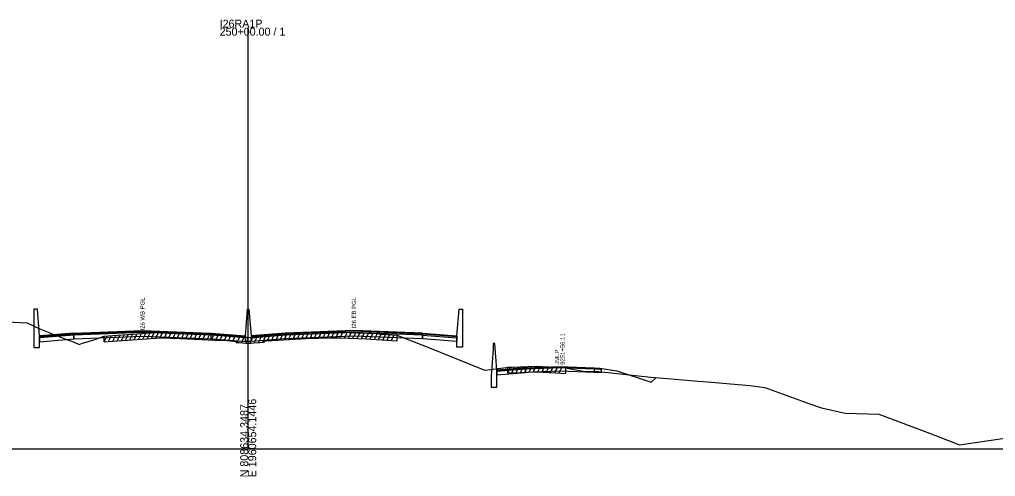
# Model space of a CAD drawing. Extents: x 1017 to 19997, y -1947 to 50737.
# Drawn here: x 10520 to 10861.4, y -9.7 to 150.1 of the extents above; entities that cross this region are included whole.
import ezdxf

# ---------------------------------------------------------------- set-up
doc = ezdxf.new("R2010")
doc.units = 0
for name, color, linetype in [('RD_GPK_XS_Cell', 7, 'Continuous'), ('RD_XS_Base', 7, 'Continuous'), ('RD_XS_ExGround', 7, 'Continuous'), ('RD_XS_ExPaveRet', 7, 'Continuous'), ('RD_XS_Greenside', 7, 'Continuous'), ('RD_XS_MedBWall', 7, 'Continuous'), ('RD_XS_Pave', 7, 'Continuous'), ('RD_XS_PaveOvlay', 7, 'Continuous'), ('RD_XS_TieSlope', 7, 'Continuous'), ('RD_XS_TX_Notes', 7, 'Continuous')]:
    doc.layers.add(name, color=color, linetype=linetype)

msp = doc.modelspace()

# ---------------------------------------------------------------- linework, layer by layer
at = {"layer": 'RD_GPK_XS_Cell'}
for p, q in [((10600, 0), (10600, 147.22)), ((10000, 0), (10600, 0)), ((10600, 0), (11200, 0))]:
    msp.add_line(p, q, dxfattribs=at)
at = {"layer": 'RD_XS_Base'}
for points in [[(10539, 39.73), (10527, 38.77)], [(10527, 38.77), (10527, 37.43)], [(10527, 37.43), (10539, 38.39)], [(10539, 38.39), (10539, 39.73)], [(10539.05, 38.39), (10539, 38.39)], [(10539.05, 39.73), (10539.05, 38.39)], [(10539.05, 38.39), (10563, 39.36), (10587, 38.39)], [(10587, 38.39), (10587, 39.73)], [(10599, 38.79), (10587, 39.73)], [(10587, 38.39), (10599, 37.45)], [(10599, 37.45), (10599, 38.79)], [(10601, 37.48), (10601, 38.82)], [(10613, 38.43), (10601, 37.48)], [(10613, 38.43), (10613, 39.77)], [(10660.95, 38.43), (10637, 39.39), (10613, 38.43)], [(10660.95, 38.43), (10660.95, 39.77)], [(10661, 38.43), (10660.95, 38.43)], [(10661, 39.77), (10661, 38.43)], [(10661, 39.76), (10673, 38.8)], [(10661, 38.42), (10661, 39.76)], [(10673, 37.46), (10661, 38.42)], [(10673, 38.8), (10673, 37.46)], [(10697, 27.96), (10687, 27.16)], [(10697, 27.96), (10709, 28.44), (10721, 27.96)], [(10697, 26.63), (10697, 27.96)], [(10721, 27.96), (10721, 26.65)], [(10721, 27.96), (10723, 27.88), (10723.5, 27.86)], [(10723.5, 27.86), (10723.5, 26.53)], [(10687, 27.16), (10687, 25.83)], [(10687, 25.83), (10697, 26.63)], [(10721, 26.65), (10709, 27.11), (10697, 26.63)], [(10723.5, 26.53), (10721, 26.65)]]:
    msp.add_lwpolyline(points, dxfattribs=at)
at = {"layer": 'RD_XS_ExGround'}
msp.add_lwpolyline([(10515.31, 44.4), (10522.73, 44.05), (10527.07, 41.88), (10535.83, 38.41), (10539.07, 37.23), (10540.82, 36.5), (10542.04, 36.89), (10545.99, 38.1), (10547.01, 38.47), (10547.59, 38.66), (10549.63, 39.34), (10554.17, 39.7), (10557.8, 40), (10564.46, 40.43), (10569.38, 40.73), (10576.24, 40.5), (10581.21, 40.35), (10588.29, 40.02), (10592.72, 39.81), (10594.75, 39.65), (10595.68, 39.56), (10595.82, 39.2), (10596.83, 39.14), (10599.13, 38.9), (10600, 38.93), (10600.9, 38.96), (10601.89, 39), (10604.09, 39.19), (10604.96, 39.27), (10605.55, 39.3), (10605.75, 39.63), (10606.43, 39.7), (10608.22, 39.86), (10616.35, 40.32), (10620.22, 40.56), (10628.65, 40.74), (10632.18, 40.8), (10641.36, 40.4), (10644.77, 40.25), (10646.7, 40.11), (10651.97, 39.73), (10662.27, 35.71), (10682.48, 27.6), (10682.87, 27.43), (10690.29, 28.45), (10690.77, 28.5), (10692.37, 28.58), (10700.69, 28.88), (10707.54, 28.58), (10710.99, 28.35), (10711.62, 28.16), (10713.46, 27.82), (10715.32, 27.48), (10717.94, 27.01), (10722.64, 26.97), (10740.83, 25.08), (10746.64, 24.55), (10757.36, 23.58), (10760.69, 23.35), (10775.49, 22.1), (10780.75, 21.38), (10796.18, 15.86), (10800.55, 14.34), (10808.85, 12.4), (10820.66, 12.1), (10838.32, 5.47), (10848.79, 1.42), (10869.31, 4.41)], dxfattribs=at)
at = {"layer": 'RD_XS_ExPaveRet'}
for p, q in [((10549.63, 37.34), (10550.67, 39.42)), ((10549.63, 37.34), (10549.63, 39.34)), ((10549.63, 37.34), (10554.17, 37.7)), ((10551.13, 37.46), (10552.17, 39.54)), ((10552.63, 37.58), (10553.67, 39.66)), ((10554.13, 37.7), (10555.17, 39.78)), ((10554.17, 37.7), (10557.8, 38)), ((10555.63, 37.82), (10556.67, 39.91)), ((10557.13, 37.94), (10558.17, 40.02)), ((10557.8, 38), (10564.46, 38.43)), ((10558.63, 38.05), (10559.66, 40.12)), ((10560.13, 38.15), (10561.16, 40.22)), ((10561.63, 38.25), (10562.66, 40.32)), ((10563.13, 38.35), (10564.16, 40.41)), ((10564.46, 38.43), (10569.38, 38.73)), ((10564.63, 38.44), (10565.66, 40.51)), ((10566.13, 38.53), (10567.16, 40.6)), ((10567.63, 38.63), (10568.66, 40.69)), ((10569.13, 38.72), (10570.12, 40.71)), ((10569.38, 38.73), (10576.24, 38.5)), ((10570.63, 38.69), (10571.61, 40.66)), ((10572.13, 38.64), (10573.11, 40.61)), ((10573.63, 38.59), (10574.61, 40.56)), ((10575.13, 38.54), (10576.11, 40.51)), ((10576.24, 38.5), (10581.21, 38.35)), ((10576.63, 38.49), (10577.61, 40.46)), ((10578.13, 38.44), (10579.11, 40.41)), ((10579.63, 38.4), (10580.61, 40.37)), ((10581.13, 38.35), (10582.1, 40.31)), ((10581.21, 38.35), (10588.29, 38.02)), ((10582.63, 38.28), (10583.6, 40.24)), ((10584.13, 38.21), (10585.1, 40.17)), ((10585.63, 38.14), (10586.6, 40.1)), ((10587.13, 38.07), (10588.1, 40.03)), ((10588.29, 38.02), (10592.72, 37.81)), ((10588.63, 38), (10589.6, 39.96)), ((10590.13, 37.93), (10591.1, 39.89)), ((10591.63, 37.86), (10592.6, 39.82)), ((10592.72, 37.81), (10594.75, 37.65)), ((10593.13, 37.78), (10594.09, 39.71)), ((10594.63, 37.66), (10595.58, 39.57)), ((10594.75, 37.65), (10595.68, 37.56)), ((10595.68, 37.56), (10595.82, 37.2)), ((10596.13, 37.18), (10597.09, 39.11)), ((10597.63, 37.05), (10598.58, 38.96)), ((10599.13, 36.9), (10600.14, 38.93)), ((10600.63, 36.95), (10601.65, 38.99)), ((10602.13, 37.02), (10603.17, 39.11)), ((10603.63, 37.15), (10604.67, 39.24)), ((10605.13, 37.27), (10606.33, 39.69)), ((10605.55, 37.3), (10605.75, 37.63)), ((10605.75, 37.63), (10606.43, 37.7)), ((10606.43, 37.7), (10608.22, 37.86)), ((10606.63, 37.71), (10607.67, 39.81)), ((10608.13, 37.85), (10609.16, 39.91)), ((10608.22, 37.86), (10616.35, 38.32)), ((10609.63, 37.94), (10610.66, 40)), ((10611.13, 38.03), (10612.16, 40.09)), ((10612.63, 38.11), (10613.66, 40.17)), ((10614.13, 38.2), (10615.16, 40.26)), ((10615.63, 38.28), (10616.66, 40.34)), ((10616.35, 38.32), (10620.22, 38.56)), ((10617.13, 38.37), (10618.16, 40.43)), ((10618.63, 38.46), (10619.66, 40.52)), ((10620.13, 38.55), (10621.14, 40.58)), ((10620.22, 38.56), (10628.65, 38.74)), ((10621.63, 38.59), (10622.64, 40.61)), ((10623.13, 38.62), (10624.14, 40.64)), ((10624.63, 38.65), (10625.64, 40.67)), ((10626.13, 38.69), (10627.14, 40.71)), ((10627.63, 38.72), (10628.64, 40.74)), ((10628.65, 38.74), (10632.18, 38.8)), ((10629.13, 38.75), (10630.13, 40.77)), ((10630.63, 38.78), (10631.63, 40.79)), ((10632.13, 38.8), (10633.11, 40.76)), ((10632.18, 38.8), (10641.36, 38.4)), ((10633.63, 38.74), (10634.6, 40.7)), ((10635.13, 38.67), (10636.1, 40.63)), ((10636.63, 38.61), (10637.6, 40.57)), ((10638.13, 38.54), (10639.1, 40.5)), ((10639.63, 38.48), (10640.6, 40.43)), ((10641.13, 38.41), (10642.1, 40.37)), ((10641.36, 38.4), (10644.77, 38.25)), ((10642.63, 38.34), (10643.6, 40.3)), ((10644.13, 38.28), (10645.1, 40.23)), ((10644.77, 38.25), (10646.7, 38.11)), ((10645.63, 38.19), (10646.59, 40.12)), ((10646.7, 38.11), (10651.97, 37.73)), ((10647.13, 38.08), (10648.09, 40.01)), ((10648.63, 37.97), (10649.59, 39.9)), ((10650.13, 37.86), (10651.09, 39.79)), ((10651.97, 39.73), (10651.97, 37.73)), ((10595.82, 37.2), (10596.83, 37.14)), ((10596.83, 37.14), (10599.13, 36.9)), ((10599.13, 36.9), (10600, 36.93)), ((10600, 36.93), (10600.9, 36.96)), ((10600.9, 36.96), (10601.89, 37)), ((10601.89, 37), (10604.09, 37.19)), ((10604.09, 37.19), (10604.96, 37.27)), ((10604.96, 37.27), (10605.55, 37.3)), ((10690.77, 26.5), (10691.79, 28.55)), ((10690.77, 26.5), (10690.77, 28.5)), ((10692.27, 26.58), (10693.29, 28.62)), ((10693.77, 26.63), (10694.78, 28.67)), ((10695.27, 26.69), (10696.28, 28.72)), ((10696.77, 26.74), (10697.78, 28.78)), ((10698.27, 26.8), (10699.28, 28.83)), ((10699.77, 26.85), (10700.78, 28.88)), ((10701.27, 26.86), (10702.24, 28.81)), ((10702.77, 26.79), (10703.74, 28.75)), ((10704.27, 26.72), (10705.24, 28.68)), ((10705.77, 26.66), (10706.74, 28.61)), ((10707.27, 26.59), (10708.24, 28.53)), ((10708.77, 26.5), (10709.73, 28.43)), ((10710.99, 28.35), (10710.99, 26.35)), ((10690.77, 26.5), (10692.37, 26.58)), ((10692.37, 26.58), (10700.69, 26.88)), ((10700.69, 26.88), (10707.54, 26.58)), ((10707.54, 26.58), (10710.99, 26.35))]:
    msp.add_line(p, q, dxfattribs=at)
at = {"layer": 'RD_XS_Greenside'}
for points in [[(10723, 28.2), (10729, 27.24)], [(10729, 27.24), (10741, 23.23)]]:
    msp.add_lwpolyline(points, dxfattribs=at)
at = {"layer": 'RD_XS_MedBWall'}
for points in [[(10527, 39.45), (10526.25, 48.79), (10525, 48.79)], [(10525, 48.79), (10525, 35.45)], [(10599, 39.45), (10599.75, 48.82), (10600.25, 48.82), (10601, 39.48)], [(10673, 39.48), (10673.75, 48.82), (10675, 48.82)], [(10675, 48.82), (10675, 35.48)], [(10527, 35.45), (10527, 39.45)], [(10599, 37.45), (10599, 39.45)], [(10601, 39.48), (10601, 37.45)], [(10673, 35.48), (10673, 39.48)], [(10525, 35.45), (10527, 35.45)], [(10601, 37.45), (10599, 37.45)], [(10675, 35.48), (10673, 35.48)], [(10685.75, 34.82), (10685, 25.48)], [(10687, 27.48), (10686.25, 36.82), (10685.75, 36.82)], [(10685.75, 36.82), (10685.75, 34.82)], [(10687, 21.48), (10687, 27.48)], [(10685, 25.48), (10685, 21.48)], [(10685, 21.48), (10687, 21.48)]]:
    msp.add_lwpolyline(points, dxfattribs=at)
at = {"layer": 'RD_XS_Pave'}
for points in [[(10539.05, 40.07), (10563, 41.03), (10587, 40.07)], [(10660.95, 40.11), (10637, 41.07), (10613, 40.11)], [(10539, 40.07), (10527, 39.11)], [(10527, 39.11), (10527, 38.77)], [(10539, 39.73), (10539, 40.07)], [(10539.05, 39.73), (10539, 39.73)], [(10587, 39.73), (10563, 40.7), (10539.05, 39.73)], [(10539.05, 39.73), (10539.05, 40.07)], [(10587, 40.07), (10587, 39.73)], [(10587, 40.07), (10599, 39.13)], [(10599, 39.13), (10599, 38.79)], [(10613, 40.11), (10601, 39.16)], [(10601, 38.82), (10613, 39.77)], [(10601, 39.16), (10601, 38.82)], [(10613, 39.77), (10637, 40.73), (10660.95, 39.77)], [(10613, 40.11), (10613, 39.77)], [(10660.95, 39.77), (10660.95, 40.11)], [(10660.95, 40.11), (10661, 40.11)], [(10661, 39.77), (10660.95, 39.77)], [(10661, 40.11), (10661, 39.77)], [(10661, 39.76), (10661, 40.1)], [(10673, 39.14), (10673, 38.8)]]:
    msp.add_lwpolyline(points, dxfattribs=at)
at = {"layer": 'RD_XS_PaveOvlay'}
for points in [[(10539.05, 40.41), (10563, 41.37), (10587, 40.41)], [(10660.95, 40.44), (10637, 41.4), (10613, 40.44)], [(10539, 40.41), (10527, 39.45)], [(10527, 39.45), (10527, 39.11)], [(10539.05, 40.41), (10539, 40.41)], [(10539, 40.41), (10539, 40.07)], [(10539, 40.07), (10539.05, 40.07)], [(10539.05, 40.07), (10539.05, 40.41)], [(10587, 40.41), (10587, 40.07)], [(10587, 40.41), (10599, 39.45)], [(10599, 39.45), (10599, 39.13)], [(10613, 40.44), (10601, 39.48)], [(10601, 39.48), (10601, 39.16)], [(10613, 40.44), (10613, 40.11)], [(10660.95, 40.11), (10660.95, 40.44)], [(10660.95, 40.44), (10661, 40.44)], [(10661, 40.44), (10661, 40.11)], [(10661, 40.44), (10673, 39.48)], [(10661, 40.1), (10661, 40.44)], [(10673, 39.14), (10661, 40.1)], [(10673, 39.48), (10673, 39.14)], [(10697, 28.28), (10687, 27.48)], [(10687, 27.16), (10697, 27.96)], [(10687, 27.48), (10687, 27.16)], [(10697, 28.28), (10709, 28.76), (10721, 28.28)], [(10721, 27.96), (10709, 28.44), (10697, 27.96)], [(10697, 27.96), (10697, 28.28)], [(10721, 28.28), (10721, 27.96)], [(10721, 28.28), (10723, 28.2)], [(10723, 27.88), (10721, 27.96)], [(10723, 28.2), (10723, 27.88)]]:
    msp.add_lwpolyline(points, dxfattribs=at)
at = {"layer": 'RD_XS_TieSlope'}
msp.add_lwpolyline([(10741, 23.23), (10742.72, 24.96)], dxfattribs=at)

# ---------------------------------------------------------------- texts
at = {"layer": 'RD_GPK_XS_Cell'}
for s, p in [('250+00.00 / 1', (10590, 144.42)), ('I26RA1P', (10590, 147.22))]:
    msp.add_text(s, height=2.8, dxfattribs=at).set_placement(p)
for s, p in [('E 1960654.1446', (10602.8, -10)), ('N 808634.3487', (10600, -10))]:
    msp.add_text(s, height=2.8, rotation=90, dxfattribs=at).set_placement(p)
at = {"layer": 'RD_XS_TX_Notes'}
for s, p in [('I26 WB PGL', (10563.75, 41.37)), ('I26 EB PGL', (10637.75, 42.13)), (' 9251+56.11', (10710.73, 28.78)), (' JMLP', (10708.77, 28.78))]:
    msp.add_text(s, height=1.5, rotation=90, dxfattribs=at).set_placement(p)

doc.saveas('drawing.dxf')
